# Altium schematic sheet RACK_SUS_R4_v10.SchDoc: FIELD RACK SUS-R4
size C; Engineer: L. Sanchez; Organization: LIGO Laboratory; Address1: California Institute of Technology; Address2: Massachusetts Institute of Technology; DocumentNumber: D1002740; Revision: v10; SheetNumber: 7; SheetTotal: 8
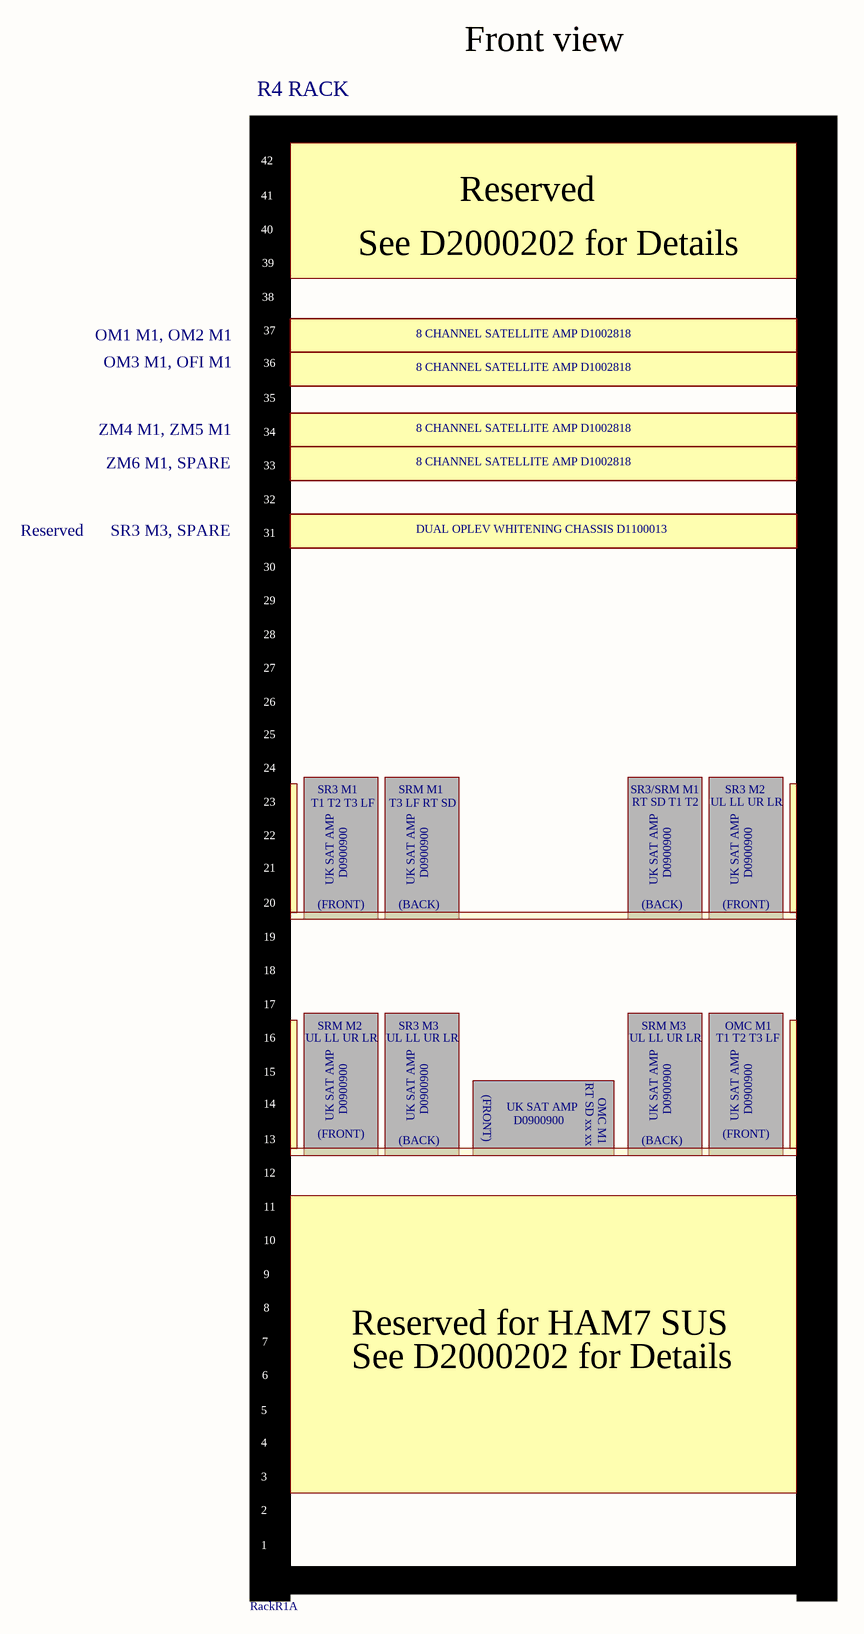
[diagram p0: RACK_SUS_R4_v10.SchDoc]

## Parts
RackR1  1U  Rack 42 pos  (value not drawn)  (part A of 2)

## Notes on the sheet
- Front view
- R4 RACK
- Reserved
- See D2000202 for Details
- OM1 M1, OM2 M1
- 8 CHANNEL SATELLITE AMP D1002818
- OM3 M1, OFI M1
- ZM4 M1, ZM5 M1
- ZM6 M1, SPARE
- SR3 M3, SPARE
- DUAL OPLEV WHITENING CHASSIS D1100013
- T1 T2 T3 LF
- SR3 M1
- T3 LF RT SD
- SRM M1
- SR3/SRM M1
- RT SD T1 T2
- UL LL UR LR
- SR3 M2
- UK SAT AMP
- D0900900
- (FRONT)
- (BACK)
- SRM M2
- SR3 M3
- RT SD xx xx
- SRM M3
- OMC M1
- Reserved for HAM7 SUS

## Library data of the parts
RackR1 = RACK_42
